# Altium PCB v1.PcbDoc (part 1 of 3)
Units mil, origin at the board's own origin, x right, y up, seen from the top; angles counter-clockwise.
Board outline 2610 x 5109 mil, 2 copper layers (Top Layer, Bottom Layer), stack 62 mil thick; 307 components, 181 nets, 763 pads, 1057 vias.
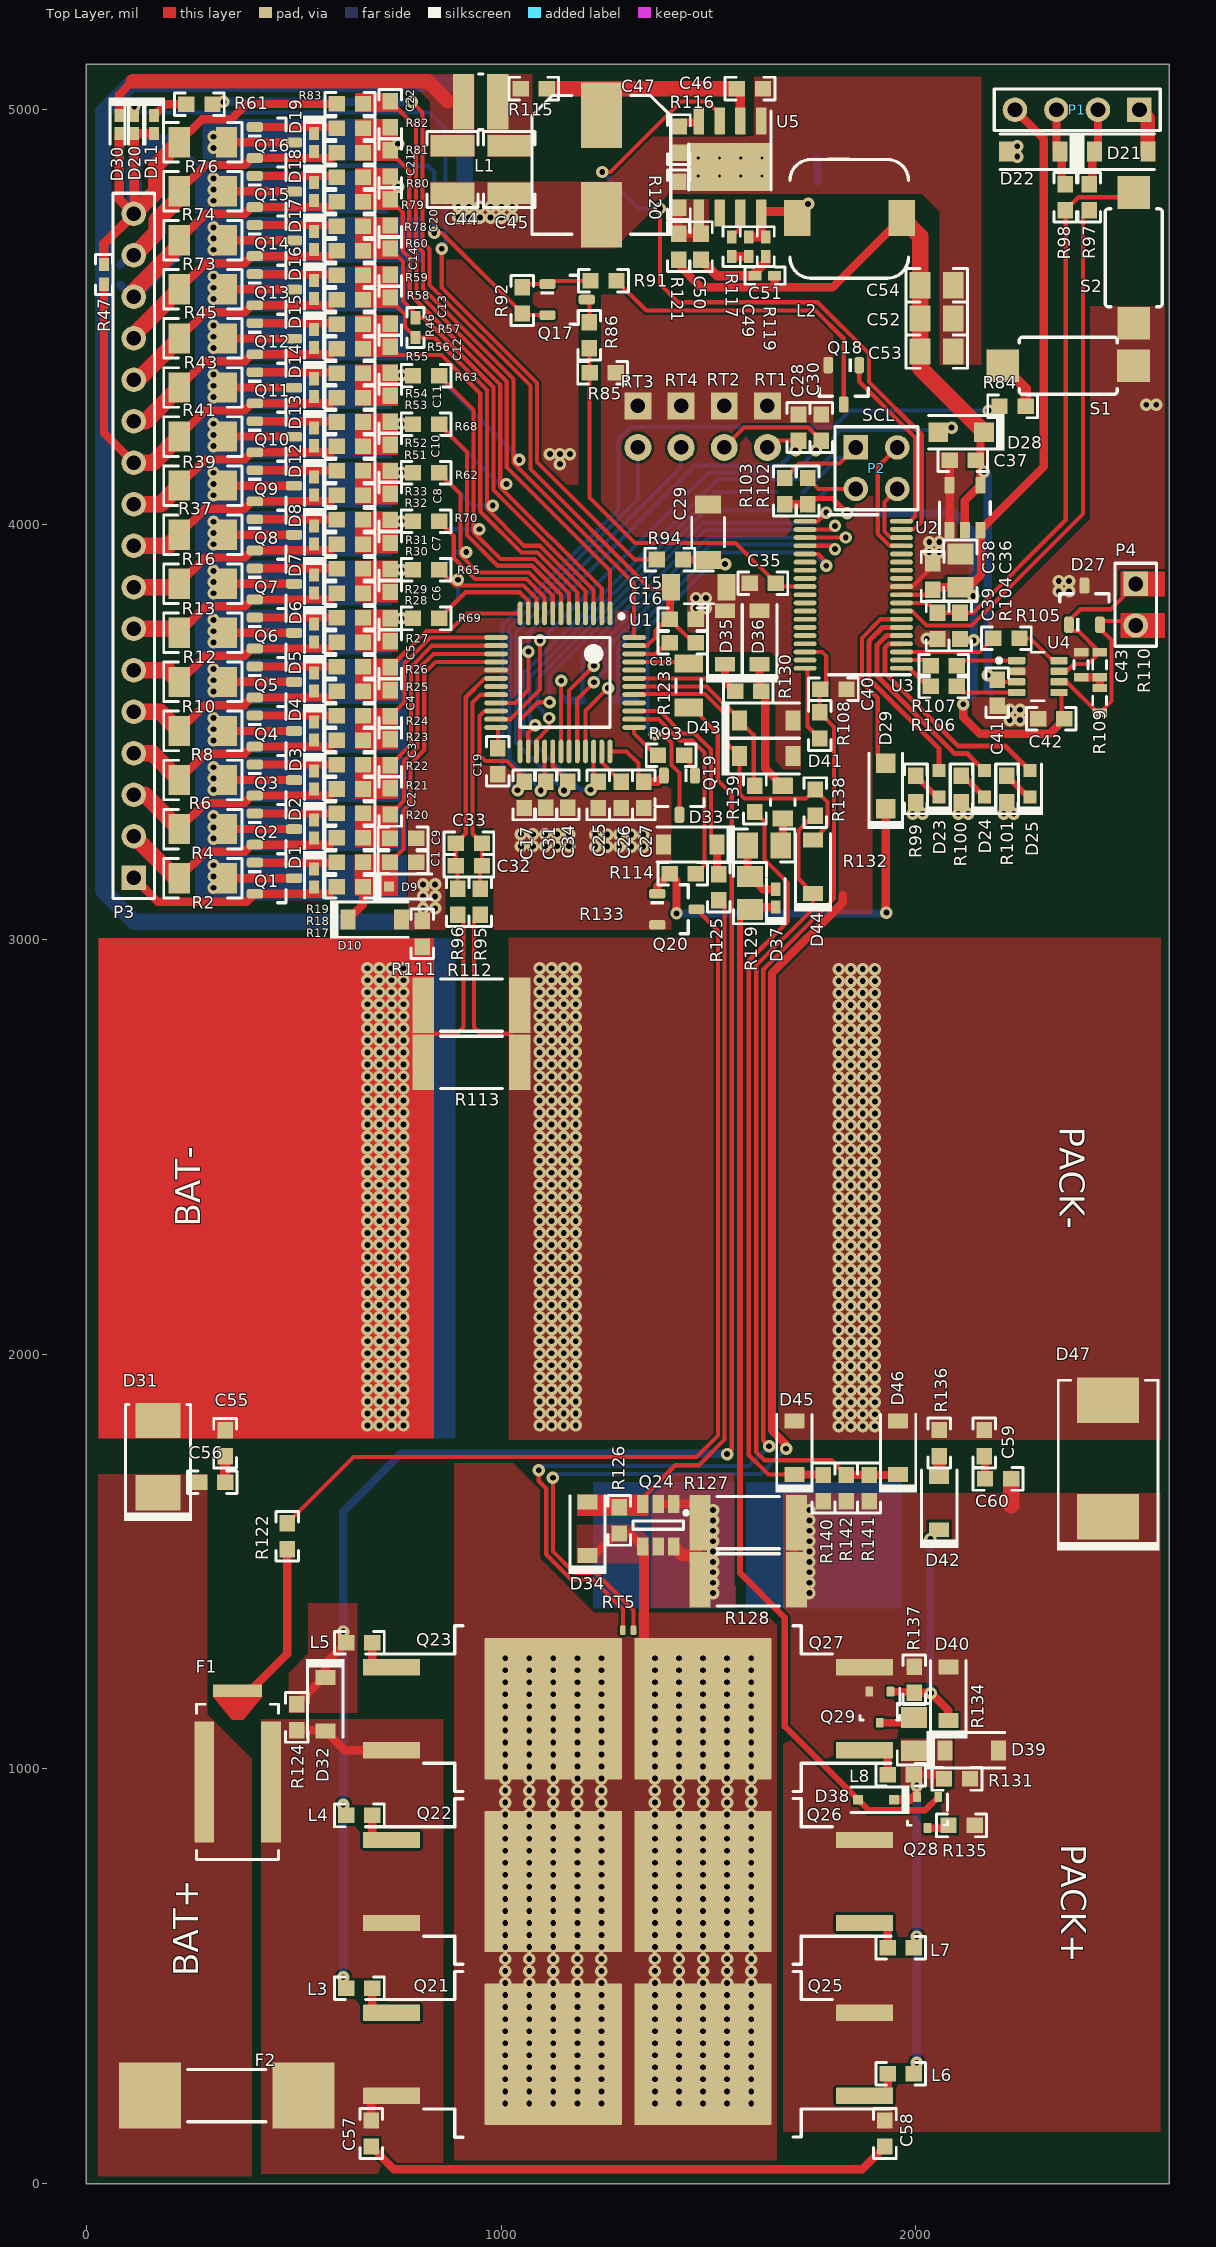
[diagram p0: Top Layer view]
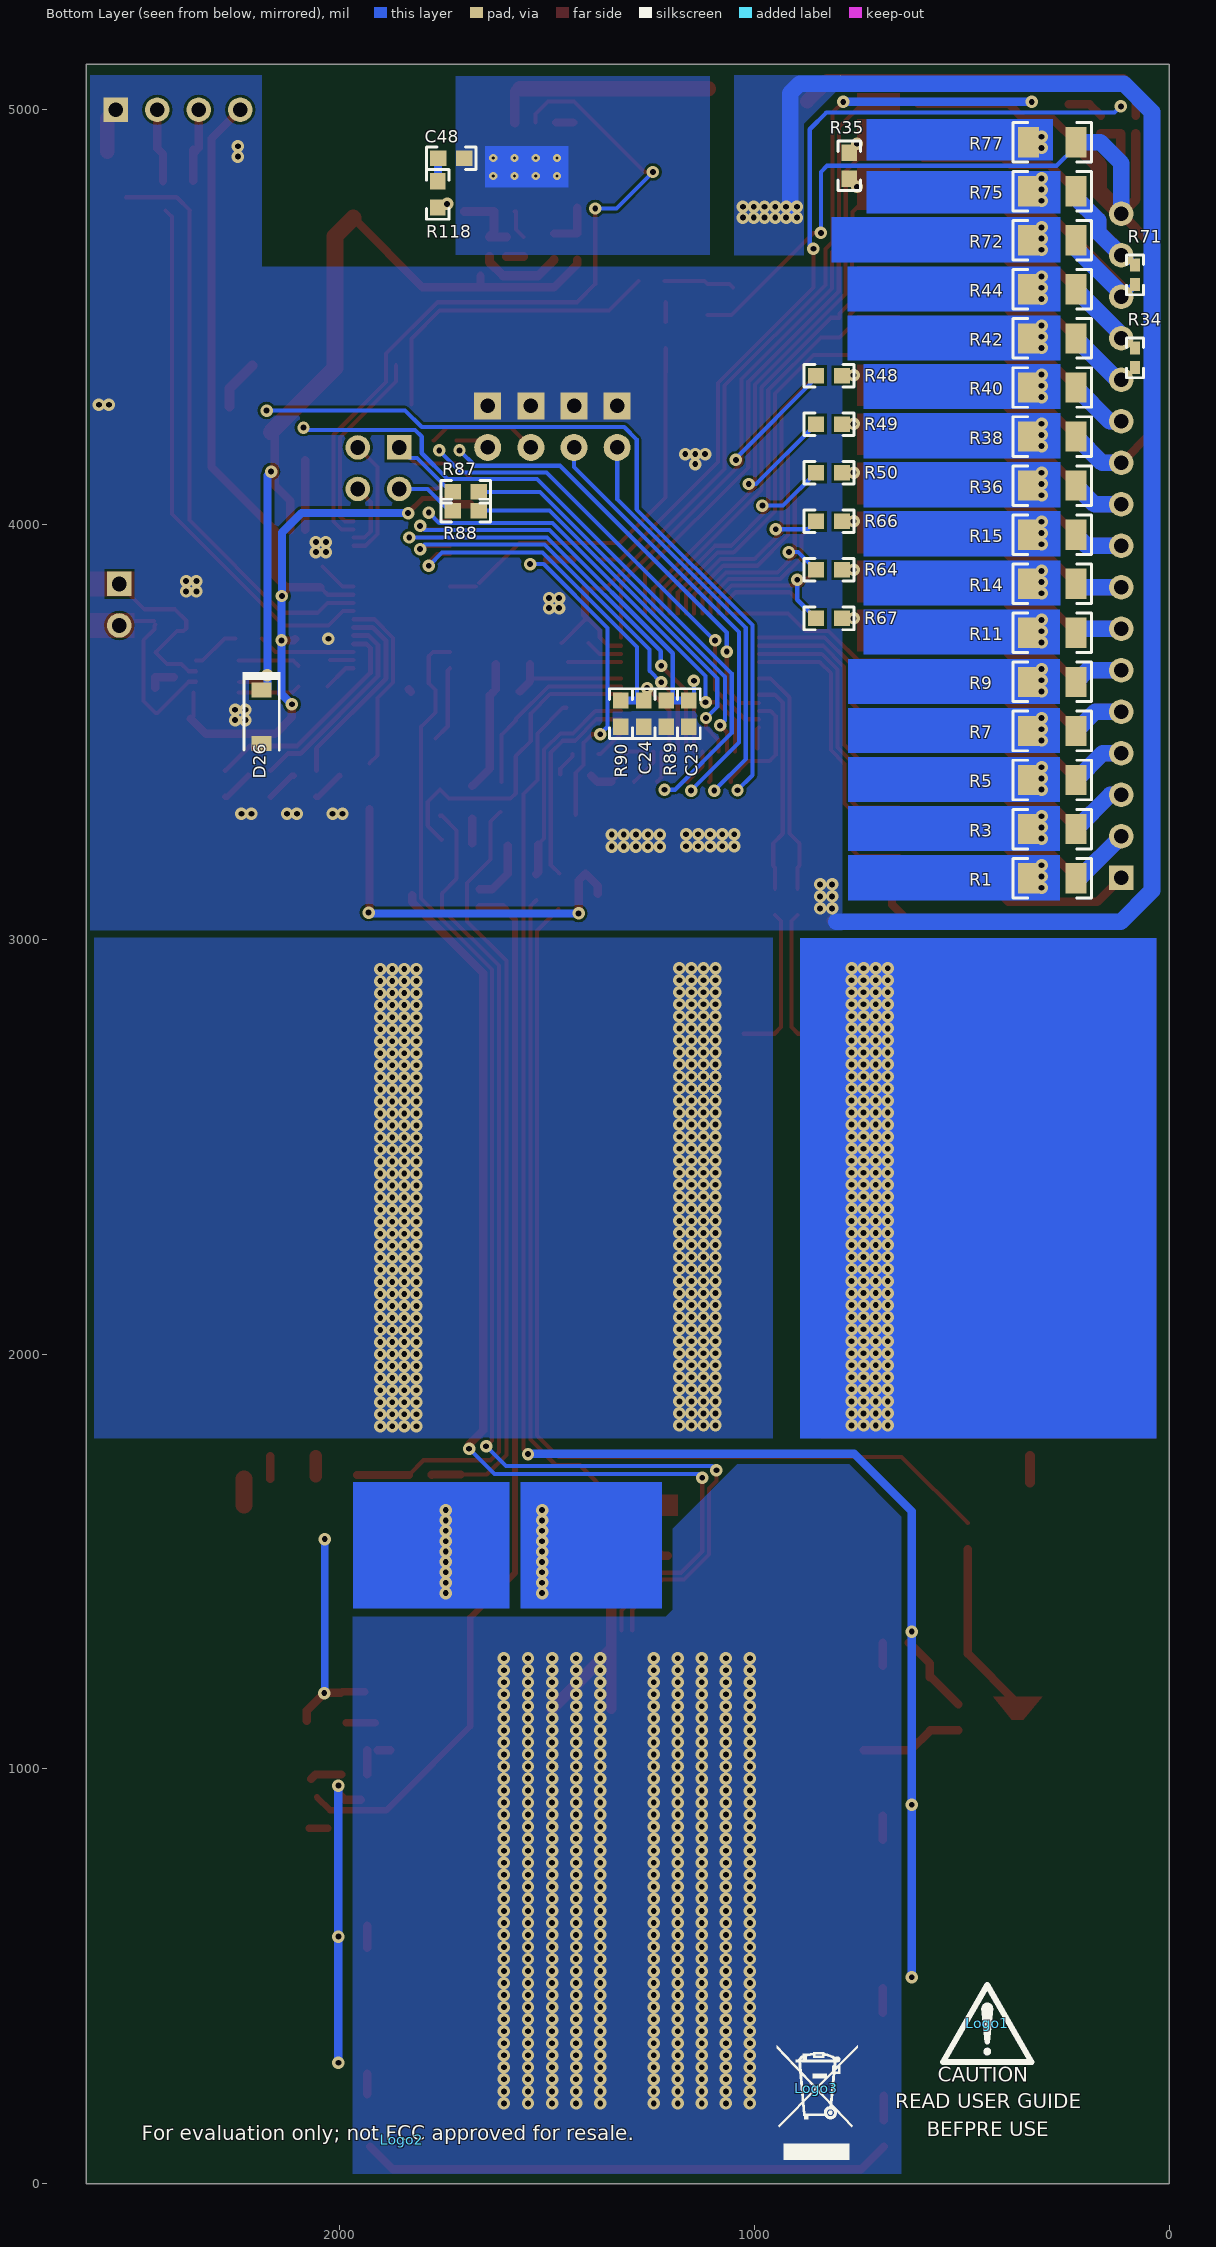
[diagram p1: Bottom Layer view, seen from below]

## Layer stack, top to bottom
Top Solder: solder mask 0.4, Solder Resist, Dk 3.5
Top Layer: signal copper 1.4
Dielectric1: core 59.2, FR-4, Dk 4.8
Bottom Layer: signal copper 1.4
Bottom Solder: solder mask 0.4, Solder Resist, Dk 3.5

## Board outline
0,0 0,5109 2610,5109 2610,0

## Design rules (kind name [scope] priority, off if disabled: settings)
AcuteAngle [All] p1: minimum=4.50000000000000E+0001 checktracksonly=FALSE
AssemblyTestPointUsage [All] p1: valid=2
BoardOutlineClearance BoardOutlineClearance_MountingHoles [OnCopper and InComponentClass('Mounting Holes')] p1 off: gap=40 ignorepadtopadclearanceinfootprint=FALSE
BoardOutlineClearance BoardOutlineClearance_Poly [OnCopper and IsPoly] p2 off: gap=25 ignorepadtopadclearanceinfootprint=FALSE
BoardOutlineClearance [OnCopper and Not InComponentClass('Logo') and not InComponentClass('FiducialMark') and not InRegion(1000,500,4000,800) and not InPoly] p3 off: gap=75 ignorepadtopadclearanceinfootprint=FALSE
Clearance Clearance_Keepouts [((IsTrack Or IsArc) And Not InPoly) And IsFree and IsKeepOut vs ((IsTrack Or IsArc) And Not InPoly) And IsFree and IsKeepOut] p1: gap=0 ignorepadtopadclearanceinfootprint=FALSE
Clearance Clearance_Poly [InPolygon] p2: gap=6 ignorepadtopadclearanceinfootprint=FALSE
Clearance Clearance_FiducialMark [IsKeepOut and InComponentClass('FiducialMark') vs IsPad and InComponentClass('FiducialMark')] p3: gap=0 ignorepadtopadclearanceinfootprint=FALSE
Clearance [All] p4: gap=6 ignorepadtopadclearanceinfootprint=FALSE
ComponentClearance ComponentClearance_MountingHoles_FiducialMarks [InComponentClass('Mounting Holes') vs InComponentClass('FiducialMark')] p1: gap=0 collisioncheckmode=3 verticalgap=10 showdistances=FALSE
ComponentClearance ComponentClearance_Shunt [InComponentClass('Header') vs InComponentClass('Shunt')] p2: gap=0 collisioncheckmode=3 verticalgap=0 showdistances=FALSE
ComponentClearance ComponentClearance_Logo [InComponentClass('Logo')] p3: gap=50 collisioncheckmode=3 verticalgap=10 showdistances=FALSE
ComponentClearance ComponentClearance_ScrewToNut [(HasFootprint('NY PMS 440 0025 PH')) vs (HasFootprint('Keystone_1902C'))] p4: gap=5 collisioncheckmode=3 verticalgap=10 showdistances=FALSE
ComponentClearance ComponentClearance_MountingHoles [InComponentClass('Mounting Holes')] p5: gap=6 collisioncheckmode=3 verticalgap=100000 showdistances=FALSE
ComponentClearance ComponentClearance_SmallPassives [HasFootprint('0201*') or HasFootprint('0402*') or HasFootprint('0508') or HasFootprint('0603*') or HasFootprint('0612') or HasFootprint('0805*') or HasFootprint('0815*') or HasFootprint('0830*') or HasFootprint('1206*') or HasFootprint('1210*') or HasFootprint('1808*') or HasFootprint('1812*') or HasFootprint('1825*') or HasFootprint('2010*') or HasFootprint('2220*') or HasFootprint('2225*') or HasFootprint('2512*') or HasFootprint('2728*') or HasFootprint('3518*') vs HasFootprint('0201*') or HasFootprint('0402*') or HasFootprint('0508') or HasFootprint('0603*') or HasFootprint('0612') or HasFootprint('0805*') or HasFootprint('0815*') or HasFootprint('0830*') or HasFootprint('1206*') or HasFootprint('1210*') or HasFootprint('1808*') or HasFootprint('1812*') or HasFootprint('1825*') or HasFootprint('2010*') or HasFootprint('2220*') or HasFootprint('2225*') or HasFootprint('2512*') or HasFootprint('2728*') or HasFootprint('3518*')] p6: gap=6 collisioncheckmode=3 verticalgap=10 showdistances=FALSE
ComponentClearance ComponentClearance_THtoSMT [IsThruComponent vs IsSMTComponent] p7: gap=6 collisioncheckmode=3 verticalgap=30 showdistances=FALSE
ComponentClearance ComponentClearance_THtoTH [IsThruComponent vs IsThruComponent] p8: gap=0 collisioncheckmode=3 verticalgap=30 showdistances=FALSE
ComponentClearance [All] p9: gap=0 collisioncheckmode=3 verticalgap=100000 showdistances=FALSE
DiffPairsRouting [All] p1: maxlimit=100 minlimit=10 mostfreqgap=10 toplayer_minwidth=15 toplayer_maxwidth=15 toplayer_prefwidth=15 bottomlayer_minwidth=15 bottomlayer_maxwidth=15 bottomlayer_prefwidth=15 maxuncoupledlength=1000
FabricationTestPointUsage TestPointUsage [All] p1: valid=2 allowmultiple=FALSE
FabricationTestpoint Testpoint [All] p1: side=3 testpointundercomponent=TRUE minsize=40 maxsize=100 preferedsize=60 minholesize=0 maxholesize=40 preferedholesize=32 testpointgrid=1 allowsidetop=TRUE allowsidebottom=TRUE usegrid=TRUE gridtolerance=0.01
FanoutControl Fanout_LCC [IsLCC] p1: bgadir=Out bgaviamode=Centered fanoutstyle=Auto fanoutdirection=Alternating viagrid=1 // Fanout_LCC (Default Rule)
FanoutControl Fanout_BGA [IsBGA] p2: bgadir=Out bgaviamode=Centered fanoutstyle=Auto fanoutdirection=Alternating viagrid=1 // Fanout_BGA (Default Rule)
FanoutControl Fanout_Default [All] p4: bgadir=Out bgaviamode=Centered fanoutstyle=Auto fanoutdirection=Alternating viagrid=1 // Fanout_Default (Default Rule)
FanoutControl Fanout_Small [(CompPinCount < 5)] p5: bgadir=Out bgaviamode=Centered fanoutstyle=Auto fanoutdirection=OutThenIn viagrid=1 // Fanout_Small (Default Rule)
HoleSize [All] p1: absolutevalues=TRUE maxlimit=251 minlimit=7.87 maxpercent=80.000 minpercent=20.000
MinimumAnnularRing MinimumAnnularRing_ThermalPadVias [IsVia and InAnyComponent] p1: minimumring=5.91
MinimumAnnularRing [All] p2: minimumring=8
MinimumSolderMaskSliver MinimumSolderMaskSliver_Logo [InComponentClass('Logo') vs InComponentClass('Logo')] p1 off: minsoldermaskwidth=0.7
MinimumSolderMaskSliver [All] p2 off: minsoldermaskwidth=3.94
PlaneConnect [All] p1: planeconnectstyle=Relief reliefexpansion=10 reliefentries=4 reliefconductorwidth=10 reliefairgap=10
PolygonConnect [All] p1: connectstyle=Direct reliefconductorwidth=10 reliefentries=4 polygonreliefangle="90 Angle" airgapwidth=10
RoutingVias ThermalPadVias [IsVia and InAnyComponent] p1: holewidth=7.87 width=19.68 viastyle="Through Hole" minholewidth=7.87 minwidth=19.68 maxholewidth=12.99 maxwidth=23.62
RoutingVias [All] p2: holewidth=16 width=34 viastyle="Through Hole" minholewidth=7.87 minwidth=26 maxholewidth=40 maxwidth=65
SilkToBoardRegionClearance [Not ((IsComment or IsDesignator) And (Hide <> 'False')) and not InRegion(1000,500,4000,800)] p1:
SilkToSilkClearance SilkToSilkClearance_Pb-FreeLogo [(HasFootprint('Pb-Free_Overlay_Medium') OR HasFootprint('Pb-Free_Overlay_Small')) vs (HasFootprint('Pb-Free_Overlay_Medium') OR HasFootprint('Pb-Free_Overlay_Small'))] p1 off: silktosilkclearance=0
SilkToSilkClearance [All] p2 off: silktosilkclearance=4
SilkToSolderMaskClearance SilkToComponentPadClearance [(IsPad or IsFill or IsRegion) and InAnycomponent] p1 off: minsilkscreentomaskgap=5 clearancetoexposedcopper=TRUE
SilkToSolderMaskClearance "Silk to Solder Mask Opening" [All] p2 off: minsilkscreentomaskgap=4 clearancetoexposedcopper=FALSE
SolderMaskExpansion [All] p1: expansion=1.97
Width [All] p1: maxlimit=100 minlimit=6 preferedwidth=10 checkconnectedcopper=TRUE
15 further rules are at their usual default settings.

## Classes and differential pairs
component class "High level sch": D28 D29 P3 P4 R111 R112 R113 R114
component class Designator: C1 C2 C3 C4 C5 C6 C7 C8 C9 C10 C11 C12 C13 C14 C15 C16 C17 C18 C19 C20 C21 C22 C23 C24 C25 C26 C27 C28 C29 C30 C31 C32 C33 C34 D1 D2 D3 D4 D5 D6 D7 D8 D9 D10 D11 D12 D13 D14 D15 D16 D17 D18 D19 D20 Q1 Q2 Q3 Q4 Q5 Q6 Q7 Q8 Q9 Q10 Q11 Q12 Q13 Q14 Q15 Q16 Q17 Q18 Q19 R1 R2 R3 R4 R5 R6 R7 R8 R9 R10 R11 R12 R13 R14 R15 R16 R17 R18 R19 R20 R21 R22 R23 R24 R25 R26 R27 R28 R29 R30 R31 R32 R33 R34 R35 R36 R37 R38 R39 R40 R41 R42 R43 R44 R45 R46 R47 R48 R49 R50 R51 R52 R53 R54 R55 R56 R57 R58 R59 R60 R61 R62 R63 R64 R65 R66 R67 R68 R69 R70 R71 R72 R73 R74 R75 R76 R77 R78 R79 R80 R81 R82 R83 R84 R85 R86 R87 R88 R89 R90 R91 R92 R93 R94 R95 R96 RT1 RT2 RT3 RT4 S1 U1

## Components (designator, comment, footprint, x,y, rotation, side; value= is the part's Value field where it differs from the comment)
C1 "GCM188R71H224KA64D" 0603 764,3185 r0 top value=0.22uF
C2 "GCM188R71H224KA64D" 0603 733,3332 r270 top value=0.22uF
C3 "GCM188R71H224KA64D" 0603 733,3450.29 r270 top value=0.22uF
C4 "GCM188R71H224KA64D" 0603 733,3568.57 r270 top value=0.22uF
C5 "GCM188R71H224KA64D" 0603 733,3686.86 r270 top value=0.22uF
C6 "GCM188R71H224KA64D" 0603 733,3805.14 r270 top value=0.22uF
C7 "GCM188R71H224KA64D" 0603 733,3923.43 r270 top value=0.22uF
C8 "GCM188R71H224KA64D" 0603 733,4041.71 r270 top value=0.22uF
C9 "GCM188R71H224KA64D" 0603 764,3243 r0 top value=0.22uF
C10 "GCM188R71H224KA64D" 0603 733,4160 r270 top value=0.22uF
C11 "GCM188R71H224KA64D" 0603 733,4278.29 r270 top value=0.22uF
C12 "GCM188R71H224KA64D" 0603 733,4396.57 r270 top value=0.22uF
C13 "GCM188R71H224KA64D" 0603 733,4514.86 r270 top value=0.22uF
C14 "GCM188R71H224KA64D" 0603 733,4633.14 r270 top value=0.22uF
C15 "CL31B225KCHSNNE" 1206_190 1477,3848 r180 top value=2.2uF
C16 "GRM1885C2A101JA01D" 0603 1438,3771 r180 top value=100pF
C17 "GRM1885C2A101JA01D" 0603 1056.34,3347.73 r270 top value=100pF
C18 "C1608X7R1E105K080AB" 0603 1438,3714 r0 top value=1uF
C19 "EMK107BB7225MA-T" 0603 992.34,3428.73 r270 top value=2.2uF
C20 "GCM188R71H224KA64D" 0603 733,4751.43 r270 top value=0.22uF
C21 "GCM188R71H224KA64D" 0603 733,4869.71 r270 top value=0.22uF
C22 "GCM188R71H224KA64D" 0603 733,4988 r270 top value=0.22uF
C23 "GRM1885C2A101JA01D" 0603 1157,3543.5 r270 bottom value=100pF
C24 "GRM1885C2A101JA01D" 0603 1266.38,3543.5 r270 bottom value=100pF
C25 "GCM188R71C105KA64D" 0603 1234.34,3347.73 r270 top value=1uF
C26 "GCM188R71C105KA64D" 0603 1289.34,3347.73 r270 top value=1uF
C27 "GRM188R71H223KA01D" 0603 1344,3347.73 r270 top value=0.022uF
C28 "GRM188R71H471KA01D" 0603 1717,4233.01 r90 top value=470pF
C29 "C3216X7R2A105K160AA" 1206_180 1499,3981 r90 top value=1uF
C30 "GRM188R71H471KA01D" 0603 1772,4233.01 r90 top value=470pF
C31 "GRM188R71H471KA01D" 0603 1108,3348 r270 top value=470pF
C32 "GRM188R71H104KA93D" 0603 922.5,3177 r0 top value=0.1uF
C33 "GRM1885C2A101JA01D" 0603 922.5,3231 r0 top value=100pF
C34 "GRM188R71H471KA01D" 0603 1161,3348 r270 top value=470pF
C35 "GRM188R71H471KA01D" 0603 1631,3858 r0 top value=470pF
C36 "CL21B106KOQNNNE" 0805_HV 2107,3888 r270 top value=10uF
C37 "EMK107BB7225MA-T" 0603 2113,4154 r180 top value=2.2uF
C38 "GRM188R71H104KA93D" 0603 2040,3873.98 r270 top value=0.1uF
C39 "GRM1885C1H102JA01D" 0603 2052,3755 r270 top value=1000pF
C40 "GRM188R71H471KA01D" 0603 1801,3602 r0 top value=470pF
C41 "GRM188R71H104KA93D" 0603 2196,3594 r270 top value=0.1uF
C42 "GRM188R71H104KA93D" 0603 2326,3531 r180 top value=0.1uF
C43 "GRM188R71H104KA93D" 0603S 2398,3661.33 r270 top value=0.1uF
C44 "C3225X7S2A475K200AE" 1210 883,4855 r270 top value=4.7uF
C45 "C3225X7S2A475K200AE" 1210 1020,4855 r270 top value=4.7uF
C46 "GRM188R72A104KA35D" 0603 1600,5050 r0 top value=0.1uF
C47 "UUX2A100MNL1GS" UUX_800x620 1242,4866 r270 top value=10uF
C48 "NC" 0603 1730,4882 r180 bottom value=56pF
C49 "GRM155R71H222KA01D" 0402 1597,4669 r90 top value=2200pF
C50 "GRM1885C1H101JA01D" 0603 1482,4669 r90 top value=100pF
C51 "GRM155R71H152KA01D" 0402 1636,4599 r180 top value=1500pF
C52 "GRM21BR71C475KA73L" 0805_HV 2050,4496 r0 top value=4.7uF
C53 "GRM21BR71C475KA73L" 0805_HV 2050,4416 r0 top value=4.7uF
C54 "GRM21BR71C475KA73L" 0805_HV 2050,4576 r0 top value=4.7uF
C55 "GRM188R72A104KA35D" 0603 335,1785 r90 top value=0.1uF
C56 "GRM188R72A104KA35D" 0603 304,1691 r0 top value=0.1uF
C57 "GRM188R72A104KA35D" 0603 687.34,121.51 r90 top value=0.1uF
C58 "GRM188R72A104KA35D" 0603 1925.2,121.51 r270 top value=0.1uF
C59 "GRM188R72A104KA35D" 0603 2164.87,1785.52 r90 top value=0.1uF
C60 "GRM188R72A104KA35D" 0603 2198,1699 r180 top value=0.1uF
D1 "BZT52C5V6T-7" SOD-523 549,3147 r270 top value=5.6V
D2 "BZT52C5V6T-7" SOD-523 549,3265.2 r270 top value=5.6V
D3 "BZT52C5V6T-7" SOD-523 549,3383.4 r270 top value=5.6V
D4 "BZT52C5V6T-7" SOD-523 549,3501.6 r270 top value=5.6V
D5 "BZT52C5V6T-7" SOD-523 549,3619.8 r270 top value=5.6V
D6 "BZT52C5V6T-7" SOD-523 549,3738 r270 top value=5.6V
D7 "BZT52C5V6T-7" SOD-523 549,3856.2 r270 top value=5.6V
D8 "BZT52C5V6T-7" SOD-523 549,3974.4 r270 top value=5.6V
D9 "BAT42WS-7-F" SOD-323 773,3127 r0 top value=30V
D10 "MMSZ4685T1G" SOD-123 696,3047 r0 top value=3.6V
D11 "BAS516,115" SOD-523 164,4963 r270 top value=100V
D12 "BZT52C5V6T-7" SOD-523 549,4092.6 r270 top value=5.6V
D13 "BZT52C5V6T-7" SOD-523 549,4210.8 r270 top value=5.6V
D14 "BZT52C5V6T-7" SOD-523 549,4329 r270 top value=5.6V
D15 "BZT52C5V6T-7" SOD-523 549,4447.2 r270 top value=5.6V
D16 "BZT52C5V6T-7" SOD-523 549,4565.4 r270 top value=5.6V
D17 "BZT52C5V6T-7" SOD-523 549,4683.6 r270 top value=5.6V
D18 "BZT52C5V6T-7" SOD-523 549,4801.8 r270 top value=5.6V
D19 "BZT52C5V6T-7" SOD-523 549,4920 r270 top value=5.6V
D20 "BAS516,115" SOD-523 116,4963 r270 top value=100V
D21 "MMSZ4685T1G" SOD-123 2494.7,4897.95 r0 top value=3.6V
D22 "MMSZ4685T1G" SOD-123 2282.7,4897.95 r180 top value=3.6V
D23 "150060RS75000" WL-SMCW_RED 2055.18,3374.5 r90 top value=Red
D24 "150060RS75000" WL-SMCW_RED 2165,3374.5 r90 top value=Red
D25 "150060RS75000" WL-SMCW_RED 2274.82,3374.5 r90 top
D26 "MMSZ4690T1G" SOD-123 2187,3536 r270 bottom value=5.6V
D27 "NUP3105LT1G" SOT-23 2406,3805 r90 top value=24V
D28 "PMEG2010AEH,115" SOD-123F 2109,4222 r180 top value=20V
D29 "PMEG2010AEH,115" SOD-123F 1927,3369 r90 top value=20V
D30 "BAS516,115" SOD-523 80,4963 r270 top value=100V
D31 "SMBJ60A-13-F" SMB 173,1753 r90 top value=60V
D32 "MMSZ5246B-7-F" SOD-123 576.52,1156.51 r270 top value=16V
D33 "MMSZ5267BT1G" SOD-123 1456,3228 r180 top value=75V
D34 "MMSZ5246B-7-F" SOD-123 1208.48,1578.47 r90 top value=16V
D35 "NC" SOD-123 1540,3727 r90 top value=75V
D36 "BAT46W-7-F" SOD-123 1623,3727 r90 top value=100V
D37 "BAS516,115" SOD-523 1662,3098.7 r90 top value=100V
D38 "BZT52C5V1S-7-F" SOD-323 1904,926 r180 top value=5.1V
D39 "MMSZ5246B-7-F" SOD-123 2134,1045 r0 top value=16V
D40 "MMSZ5246B-7-F" SOD-123 2078,1181 r90 top value=16V
D41 "MMSZ5267BT1G" SOD-123 1639,3441 r0 top value=75V
D42 "BAT46W-7-F" SOD-123 2056,1641 r90 top value=100V
D43 "MMSZ5267BT1G" SOD-123 1639,3527 r0 top value=75V
D44 "BAT46W-7-F" SOD-123 1752,3175 r90 top value=100V
D45 "BAT46W-7-F" SOD-123 1707,1774 r90 top value=100V
D46 "BAT46W-7-F" SOD-123 1957,1774 r90 top value=100V
D47 "ES3D-E3/57T" SMC 2463,1748 r90 top value=200V
F1 "NC" FUSE_SFK-xx30x 365,969 r270 top
F2 "0678L9300-02" Fuse_0678L 339,213 r180 top
L1 "74438335010" WE-MAPI_3015 951,5018 r0 top value=1uH
L2 "744777168" WE-PD_7345 1840,4738 r0 top value=68uH
L3 "74279265" 0603 658.52,471.51 r0 top value="600 ohm"
L4 "74279265" 0603 658.52,888.01 r0 top value="600 ohm"
L5 "74279265" 0603 658.52,1304.51 r0 top value="600 ohm"
L6 "74279265" 0603 1963.52,265.51 r180 top value="600 ohm"
L7 "74279265" 0603 1963.52,569.51 r180 top value="600 ohm"
L8 "74279265" 0603 1963.52,986.51 r180 top value="600 ohm"
Logo1 "CAUTION.  READ USER GUIDE BEFORE USE" IEC_Caution_Small 438,387 r180 bottom
Logo2 "FCC disclaimer" FCC_disclaimer 1849,107 r180 bottom
Logo3 "WEEE logo" WEEE_Minimum 850,230 r180 bottom
P1 "Header 4" HDR1X4 2538.7,4998.95 r180 top
P2 "Header 2X2" HDR2X2 1855,4185 r270 top
P3 "Header 17" HDR1X17 115,3148 r90 top
P4 "Header 2" HDR1X2 2530,3856 r270 top
Q1 "DMG2302UK-7" SOT-23 454,3147 r0 top value=20V
Q2 "DMG2302UK-7" SOT-23 454,3265.2 r0 top value=20V
Q3 "DMG2302UK-7" SOT-23 454,3383.4 r0 top value=20V
Q4 "DMG2302UK-7" SOT-23 454,3501.6 r0 top value=20V
Q5 "DMG2302UK-7" SOT-23 454,3619.8 r0 top value=20V
Q6 "DMG2302UK-7" SOT-23 454,3738 r0 top value=20V
Q7 "DMG2302UK-7" SOT-23 454,3856.2 r0 top value=20V
Q8 "DMG2302UK-7" SOT-23 454,3974.4 r0 top value=20V
Q9 "DMG2302UK-7" SOT-23 454,4092.6 r0 top value=20V
Q10 "DMG2302UK-7" SOT-23 454,4210.8 r0 top value=20V
Q11 "DMG2302UK-7" SOT-23 454,4329 r0 top value=20V
Q12 "DMG2302UK-7" SOT-23 454,4447.2 r0 top value=20V
Q13 "DMG2302UK-7" SOT-23 454,4565.4 r0 top value=20V
Q14 "DMG2302UK-7" SOT-23 454,4683.6 r0 top value=20V
Q15 "DMG2302UK-7" SOT-23 454,4801.8 r0 top value=20V
Q16 "DMG2302UK-7" SOT-23 454,4920 r0 top value=20V
Q17 "ZXMP10A13FTA" SOT-23 1159.3,4541.32 r0 top value=-100V
Q18 "BSS123" SOT-23 1826,4336 r270 top value=100V
Q19 "ZXTN25100BFHTA" SOT-23 1430,3347 r270 top value="100 V"
Q20 "DMN10H220L-7" SOT-23 1424,3072 r0 top value=100V
Q21 "CSD19536KTT" KTT0002A_N 978.43,312.4 r0 top value=100V
Q22 "CSD19536KTT" KTT0002A_N 978.43,728.9 r0 top value=100V
Q23 "CSD19536KTT" KTT0002A_N 978.43,1145.4 r0 top value=100V
Q24 "FDC3535" SSOT-6 1379,1587.82 r270 top value=-80V
Q25 "CSD19536KTT" KTT0002A_N 1634.12,312.5 r180 top value=100V
Q26 "CSD19536KTT" KTT0002A_N 1634.12,729 r180 top value=100V
Q27 "CSD19536KTT" KTT0002A_N 1634.12,1145.5 r180 top value=100V
Q28 "DMG1013UW-7" SOT-323 2028,895 r270 top value=-20V
Q29 "2N7002W-7-F" SOT-323 1913,1149 r270 top value=60V
R1 "CRCW120680R6FKEA" 1206 281.53,3147 r0 bottom value=80.6
R2 "CRCW120680R6FKEA" 1206 281.53,3147 r0 top value=80.6
R3 "CRCW120680R6FKEA" 1206 281.53,3265.26 r0 bottom value=80.6
R4 "CRCW120680R6FKEA" 1206 281.53,3265.26 r0 top value=80.6
R5 "CRCW120680R6FKEA" 1206 281.53,3383.51 r0 bottom value=80.6
R6 "CRCW120680R6FKEA" 1206 281.53,3383.51 r0 top value=80.6
R7 "CRCW120680R6FKEA" 1206 281.53,3501.77 r0 bottom value=80.6
R8 "CRCW120680R6FKEA" 1206 281.53,3501.77 r0 top value=80.6
R9 "CRCW120680R6FKEA" 1206 281.53,3620.03 r0 bottom value=80.6
R10 "CRCW120680R6FKEA" 1206 281.53,3620.03 r0 top value=80.6
R11 "CRCW120680R6FKEA" 1206 281.53,3738.29 r0 bottom value=80.6
R12 "CRCW120680R6FKEA" 1206 281.53,3738.29 r0 top value=80.6
R13 "CRCW120680R6FKEA" 1206 281.53,3856.54 r0 top value=80.6
R14 "CRCW120680R6FKEA" 1206 281.53,3856.54 r0 bottom value=80.6
R15 "CRCW120680R6FKEA" 1206 281.53,3974.8 r0 bottom value=80.6
R16 "CRCW120680R6FKEA" 1206 281.53,3974.8 r0 top value=80.6
R17 "CRCW0603100RFKEA" 0603 636,3126 r0 top value=100
R18 "CRCW060310K0JNEA" 0603 636,3184.97 r0 top value=10k
R19 "CRCW0603100RFKEA" 0603 636,3243.94 r0 top value=100
R20 "CRCW060310K0JNEA" 0603 636,3302.9 r0 top value=10k
R21 "CRCW0603100RFKEA" 0603 636,3361.87 r0 top value=100
R22 "CRCW060310K0JNEA" 0603 636,3420.84 r0 top value=10k
R23 "CRCW0603100RFKEA" 0603 636,3479.81 r0 top value=100
R24 "CRCW060310K0JNEA" 0603 636,3538.77 r0 top value=10k
R25 "CRCW0603100RFKEA" 0603 636,3597.74 r0 top value=100
R26 "CRCW060310K0JNEA" 0603 636,3656.71 r0 top value=10k
R27 "CRCW0603100RFKEA" 0603 636,3715.68 r0 top value=100
R28 "CRCW060310K0JNEA" 0603 636,3774.64 r0 top value=10k
R29 "CRCW0603100RFKEA" 0603 636,3833.61 r0 top value=100
R30 "CRCW060310K0JNEA" 0603 636,3892.58 r0 top value=10k
R31 "CRCW0603100RFKEA" 0603 636,3951.55 r0 top value=100
R32 "CRCW060310K0JNEA" 0603 636,4010.52 r0 top value=10k
R33 "CRCW0603100RFKEA" 0603 636,4069.48 r0 top value=100
R34 "CRCW04020000Z0ED" 0402 82,4401 r90 bottom value=0
R35 "CRCW06030000Z0EA" 0603 771,4864 r270 bottom value=0
R36 "CRCW120680R6FKEA" 1206 281.53,4093.06 r0 bottom value=80.6
R37 "CRCW120680R6FKEA" 1206 281.53,4093.06 r0 top value=80.6
R38 "CRCW120680R6FKEA" 1206 281.53,4211.32 r0 bottom value=80.6
R39 "CRCW120680R6FKEA" 1206 281.53,4211.32 r0 top value=80.6
R40 "CRCW120680R6FKEA" 1206 281.53,4329.57 r0 bottom value=80.6
R41 "CRCW120680R6FKEA" 1206 281.53,4329.57 r0 top value=80.6
R42 "CRCW120680R6FKEA" 1206 281.53,4447.83 r0 bottom value=80.6
R43 "CRCW120680R6FKEA" 1206 281.53,4447.83 r0 top value=80.6
R44 "CRCW120680R6FKEA" 1206 281.53,4566.09 r0 bottom value=80.6
R45 "CRCW120680R6FKEA" 1206 281.53,4566.09 r0 top value=80.6
R46 "CRCW04020000Z0ED" 0402 794,4474 r90 top value=0
R47 "CRCW04020000Z0ED" 0402 43,4602 r270 top value=0
R48 "CRCW06030000Z0EA" 0603 819.5,4358 r0 bottom value=0
R49 "CRCW06030000Z0EA" 0603 819.5,4241 r0 bottom value=0
R50 "CRCW06030000Z0EA" 0603 819.5,4124 r0 bottom value=0
R51 "CRCW060310K0JNEA" 0603 636,4128.45 r0 top value=10k
R52 "CRCW0603100RFKEA" 0603 636,4187.42 r0 top value=100
R53 "CRCW060310K0JNEA" 0603 636,4246.39 r0 top value=10k
R54 "CRCW0603100RFKEA" 0603 636,4305.35 r0 top value=100
R55 "CRCW060310K0JNEA" 0603 636,4364.32 r0 top value=10k
R56 "CRCW0603100RFKEA" 0603 636,4423.29 r0 top value=100
R57 "CRCW060310K0JNEA" 0603 636,4482.26 r0 top value=10k
R58 "CRCW0603100RFKEA" 0603 636,4541.22 r0 top value=100
R59 "CRCW060310K0JNEA" 0603 636,4600.19 r0 top value=10k
R60 "CRCW0603100RFKEA" 0603 636,4659.16 r0 top value=100
R61 "CRCW0603100RFKEA" 0603 273,5012 r0 top value=100
R62 "CRCW06030000Z0EA" 0603 819.5,4123.97 r0 top value=0
R63 "CRCW06030000Z0EA" 0603 819.5,4358 r0 top value=0
R64 "CRCW06030000Z0EA" 0603 819.5,3890 r0 bottom value=0
R65 "CRCW06030000Z0EA" 0603 819.5,3890.01 r180 top value=0
R66 "CRCW06030000Z0EA" 0603 819.5,4007 r0 bottom value=0
R67 "CRCW06030000Z0EA" 0603 819.5,3773 r0 bottom value=0
R68 "CRCW06030000Z0EA" 0603 819.5,4241.05 r180 top value=0
R69 "CRCW06030000Z0EA" 0603 819.5,3773 r180 top value=0
R70 "CRCW06030000Z0EA" 0603 819.5,4007.03 r180 top value=0
R71 "CRCW04020000Z0ED" 0402 82,4601 r90 bottom value=0
R72 "CRCW120680R6FKEA" 1206 281.53,4684.34 r0 bottom value=80.6
R73 "CRCW120680R6FKEA" 1206 281.53,4684.34 r0 top value=80.6
R74 "CRCW120680R6FKEA" 1206 281.53,4802.6 r0 top value=80.6
R75 "CRCW120680R6FKEA" 1206 281.53,4802.6 r0 bottom value=80.6
R76 "CRCW120680R6FKEA" 1206 281.53,4920.86 r0 top value=80.6
R77 "CRCW120680R6FKEA" 1206 281.53,4920.86 r0 bottom value=80.6
R78 "CRCW060310K0JNEA" 0603 636,4718.13 r0 top value=10k
R79 "CRCW0603100RFKEA" 0603 636,4777.1 r0 top value=100
R80 "CRCW060310K0JNEA" 0603 636,4836.06 r0 top value=10k
R81 "CRCW0603100RFKEA" 0603 636,4895.03 r0 top value=100
R82 "CRCW060310K0JNEA" 0603 636,4954 r0 top value=10k
R83 "CRCW0603100RFKEA" 0603 636,5013 r0 top value=100
R84 "CRCW060310K0JNEA" 0603 2233,4284 r180 top value=10k
R85 "RT0603DRE0713K3L" 0603 1245,4365.5 r180 top value=13.3k
R86 "RT0603DRE07665KL" 0603 1213,4455.5 r90 top value=665k
R87 "CRCW0603100RFKEA" 0603 1695,4078 r180 bottom value=100
R88 "CRCW0603100RFKEA" 0603 1695,4033 r180 bottom value=100
R89 "CRCW060310K0JNEA" 0603 1211.62,3543.5 r90 bottom value=10k
R90 "CRCW060310K0JNEA" 0603 1321,3543.5 r90 bottom value=10k
R91 "CRCW06033M30JNEA" 0603 1247,4586.5 r180 top value=3.3Meg
R92 "CRCW06031M00JNEA" 0603 1051.3,4539.32 r270 top value=1.0Meg
R93 "CRCW0603100RFKEA" 0603 1410,3443 r0 top value=100
R94 "RC0603FR-07249RL" 0603 1407,3915 r180 top value=249
R95 "CRCW0603100RFKEA" 0603 949.5,3090 r90 top value=100
R96 "CRCW0603100RFKEA" 0603 895.5,3090 r90 top value=100
R97 "CRCW0603100RFKEA" 0603 2417.47,4787.95 r90 top value=100
R98 "CRCW0603100RFKEA" 0603 2360,4787.95 r90 top value=100
R99 "RC0603FR-07470RL" 0603 1999.54,3362.19 r90 top value=470
R100 "RC0603FR-07470RL" 0603 2109.36,3362.19 r90 top value=470
R101 "RC0603FR-07470RL" 0603 2219.18,3362.19 r90 top value=470
R102 "CRCW060310K0JNEA" 0603 1739,4080 r90 top value=10k
R103 "CRCW060310K0JNEA" 0603 1684,4080 r90 top value=10k
R104 "RC0603FR-0747KL" 0603 2106.2,3755 r270 top value=47.0k
R105 "CRCW0603100RFKEA" 0603 2218,3725 r180 top value=100
R106 "CRCW0603100RFKEA" 0603 2067,3609 r180 top value=100
R107 "CRCW0603100RFKEA" 0603 2067,3659 r180 top value=100
R108 "CRCW060310K0FKEA" 0603 1768,3515 r270 top value=10.0k
R109 "RC0603FR-0760R4L" 0603S 2443,3575.33 r270 top value=60.4
R110 "RC0603FR-0760R4L" 0603S 2443,3661.33 r270 top value=60.4
R111 "CRCW06030000Z0EA" 0603 810,3013 r270 top value=0
R112 "CSNL2512FT2L00" 2512 929,2841 r0 top value=0.002
R113 "CSNL2512FT2L00" 2512 929,2703 r0 top value=0.002
R114 "CRCW06035K10JNEA" 0603 1438,3158 r180 top value=5.1k
R115 "CRCW06030000Z0EA" 0603 1079,5050 r0 top value=0
R116 "CRCW060382K5FKEA" 0603 1429,4927 r90 top value=82.5k
R117 "CRCW04020000Z0ED" 0402 1556,4669 r270 top value=0
R118 "NC" 0603 1762.78,4795 r270 bottom value=499k
R119 "RC0402FR-07523KL" 0402 1638,4669 r270 top value=523k
R120 "CRCW060363K4FKEA" 0603 1428.93,4794 r270 top value=63.4k
R121 "CRCW0603200KFKEA" 0603 1428.93,4669 r270 top value=200k
R122 "CRCW0603200RFKEA" 0603 485,1561 r90 top value=200
R123 "ERJ-8ENF4990V" 1206L 1452,3611 r270 top value=499
R124 "CRCW060310M0JNEA" 0603 507.52,1124.51 r270 top value=10Meg
R125 "RT0603BRD0749K9L" 0603 1525,3125.22 r270 top value=49.9k
R126 "CRCW06031M00JNEA" 0603 1285.11,1599.14 r270 top value=1.0Meg
R127 "RC2512JK-07510RL" 2512 1596,1594 r180 top value=510
R128 "RC2512JK-07510RL" 2512 1596,1456 r180 top value=510
R129 "RC0805JR-0756KL" 0805_HV 1600,3111.2 r270 top value=56k
R130 "CRCW0603100RFKEA" 0603 1596,3597 r0 top value=100
R131 "CRCW060310M0JNEA" 0603 2099,976 r0 top value=10Meg
R132 "CRCW0805511RFKEA" 0805_HV1 1679,3330 r270 top value=511
R133 "CRCW0805511RFKEA" 0805_HV 1634,3225.5 r0 top value=511
R134 "CRCW0805511RFKEA" 0805_HV 1995,1084 r90 top value=511
R135 "CRCW0603511RFKEA" 0603 2110,864 r0 top value=511
R136 "CRCW060310K0JNEA" 0603 2056,1785.52 r270 top value=10k
R137 "CRCW060310M0JNEA" 0603 1996,1215 r270 top value=10Meg
R138 "RT0603BRD0749K9L" 0603 1757,3329 r270 top value=49.9k
R139 "CRCW06035K10JNEA" 0603 1612,3338 r270 top value=5.1k
R140 "RT0603BRD0749K9L" 0603 1777,1677 r270 top value=49.9k
R141 "CRCW060320K0JNEA" 0603 1887,1677 r270 top value=20k
R142 "CRCW060320K0JNEA" 0603 1832,1677 r270 top value=20k
RT1 "MF51E103F3950" Thermistor_103AT-2 1642,4235 r270 top value="10.0k ohm"
RT2 "MF51E103F3950" Thermistor_103AT-2 1538,4235 r270 top value="10.0k ohm"
RT3 "MF51E103F3950" Thermistor_103AT-2 1330,4235 r270 top value="10.0k ohm"
RT4 "MF51E103F3950" Thermistor_103AT-2 1434,4235 r270 top value="10.0k ohm"
RT5 "TMP6131DECR" DEC0002A 1306.52,1334.51 r180 top
S1 "RS-032G05A3-SM RT" SW_RS-032G05A3-SM 2367,4382 r0 top
S2 "RS-032G05A3-SM RT" SW_RS-032G05A3-SM 2525,4642 r270 top
U1 "bq76952PFBR" PFB0048A_N 1154.34,3618.73 r270 top
U2 "TLV70433DBVT" DBV0005A_N 2118,4040 r90 top
U3 "MSP430FR2155TDBTR" DBT0038A_N 1849,3830 r180 top
U4 "TCAN1044DDFRQ1" DDF0008A-MFG 2294,3633 r0 top
U5 "LM5163DDAR" DDA0008E_M 1552,4861 r270 top

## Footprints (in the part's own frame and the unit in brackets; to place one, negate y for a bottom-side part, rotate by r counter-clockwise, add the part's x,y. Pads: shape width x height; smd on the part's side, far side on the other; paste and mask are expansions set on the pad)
0402 [mm] "0402 from SM-752 data"
  rect 0.8x0.6 smd: 1(-0.6,0) 2(0.6,0)
  silkscreen extent -1.22,-0.52 1.22,0.52, body extent -0.55,-0.3 0.55,0.3, height 0.6
0603 [mm] "0603 from SM-752 data"
  rect 1x0.95 smd: 1(-0.8,0) 2(0.8,0)
  silkscreen extent -1.52,-0.69 1.52,0.69, body extent -0.87,-0.47 0.87,0.47, height 1
0603S [mil]
  rect 20x35 smd: 1(-30,0) 2(30,0)
  silkscreen extent -10,-17 10,17, body extent -34,-19 34,19, height 39
0805_HV [mil] "0805 with 30mil clearance between pads"
  rect 50x63 smd: 1(-40,0) 2(40,0)
  silkscreen extent -74,-40 74,40, body extent -43,-29 43,29, height 57
0805_HV1 [mm] "Custom footprint based on analyzing multiple manufacturer recommendations"
  rrect10% 1x1.25 smd: 1(-1,0) 2(1,0)
  silkscreen extent -0.2,-0.75 0.2,0.75, body extent -1.1,-0.72 1.1,0.73, height 1.45
1206 [mm] "1206 from SM-752 data"
  rect 1.3x1.85 smd: 1(-1.45,0) 2(1.45,0)
  silkscreen extent -2.4,-1.21 2.4,1.21, body extent -1.7,-0.9 1.7,0.9, height 1.35
1206_180 [mm] "1206_180"
  rect 1.1x1.6 smd: 1(-1.7,0) 2(1.7,0)
  silkscreen extent -0.9,-1 0.9,1, body extent -1.75,-0.95 1.75,0.95, height 1.8
1206_190 [mm] "1206_190"
  rect 1.1x1.6 smd: 1(-1.7,0) 2(1.7,0)
  silkscreen extent -0.9,-1 0.9,1, body extent -1.75,-0.95 1.75,0.95, height 1.9
1206L [mm] "1206 from SM-752 data"
  rect 1.1x1.75 smd: 1(-1.35,0) 2(1.35,0)
  silkscreen extent -0.4,-0.77 0.4,0.77, body extent -1.7,-0.9 1.7,0.9, height 1.35
1210 [mm] "1210 from SM-752 data"
  rect 1.3x2.7 smd: 1(-1.45,0) 2(1.45,0)
  silkscreen extent -2.32,-1.57 2.32,1.57, body extent -1.7,-1.35 1.7,1.35, height 1.35
2512 [mm] "Chip Resistor, Body 6.3x3.2mm, IPC Medium Density"
  rect 1.3x3.4 smd: 1(-2.95,0) 2(2.95,0)
  silkscreen extent -1.9,-1.6 1.9,1.6, body extent -3.22,-1.67 3.22,1.67, height 0.71
DBT0038A_N [mm] "TSSOP, 38-Leads, Body 9.7x4.4mm, Pitch 0.5mm, IPC Medium Density"
  oval 1.4x0.3 smd: 1(-2.95,4.5) 2(-2.95,4) 3(-2.95,3.5) 4(-2.95,3) 5(-2.95,2.5) 6(-2.95,2) 7(-2.95,1.5) 8(-2.95,1) 9(-2.95,0.5) 10(-2.95,0) 11(-2.95,-0.5) 12(-2.95,-1) 13(-2.95,-1.5) 14(-2.95,-2) 15(-2.95,-2.5) 16(-2.95,-3) 17(-2.95,-3.5) 18(-2.95,-4) 19(-2.95,-4.5) 20(2.95,-4.5) 21(2.95,-4) 22(2.95,-3.5) 23(2.95,-3) 24(2.95,-2.5) 25(2.95,-2) 26(2.95,-1.5) 27(2.95,-1) 28(2.95,-0.5) 29(2.95,0) 30(2.95,0.5) 31(2.95,1) 32(2.95,1.5) 33(2.95,2) 34(2.95,2.5) 35(2.95,3) 36(2.95,3.5) 37(2.95,4) 38(2.95,4.5)
  silkscreen extent -3.5,-4.9 1.5,4.9, body extent -3.21,-4.85 3.21,4.85, height 1.2
DBV0005A_N [mm] "SOT23, 5-Leads, Body 2.9x1.6mm, Pitch 0.95mm, Lead Span 2.8mm, IPC Medium Density"
  rrect17% 1x0.6 smd: 1(-1.375,0.95) 2(-1.375,0) 3(-1.375,-0.95) 4(1.375,-0.95) 5(1.375,0.95)
  silkscreen extent -1.63,-1.55 0.38,1.55, body extent -1.42,-1.46 1.42,1.46, height 1.09
DDA0008E_M [mm]
  rrect15% 1.65x0.65 smd: 1(-2.825,1.905) 2(-2.825,0.635) 3(-2.825,-0.635) 4(-2.825,-1.905) 5(2.825,-1.905) 6(2.825,-0.635) 7(2.825,0.635) 8(2.825,1.905)
  rrect7% 2.95x4.9 smd paste-1.5 mask-1.5: 9(0,0)
  rrect4% 2.4x3.1 on Top Paste: 9(0,0)
  rrect4% 2.4x3.1 on Top Solder: 9(0,0)
  silkscreen extent -3.42,-2.52 1.4,2.5, body extent -3,-2.45 3,2.45, height 1.57
DDF0008A-MFG [mm]
  rrect22% 1.05x0.45 smd paste+0 mask+0: 1(-1.3,0.975) 2(-1.3,0.325) 3(-1.3,-0.325) 4(-1.3,-0.975) 5(1.3,-0.975) 6(1.3,-0.325) 7(1.3,0.325) 8(1.3,0.975)
  silkscreen extent -2.5,-1.48 0.4,1.48, body extent -1.92,-1.73 1.92,1.73, height 0.25
DEC0002A [mm] "X1SON-2"
  rrect57% 0.35x0.6 smd paste-0.5 mask-0.05: 1(-0.325,0) 2(0.325,0)
  rrect33% 0.3x0.5 on Top Paste: 1S(-0.35,0) 2S(0.35,0)
  body extent -0.5,-0.3 0.5,0.3, height 0.5
FCC_disclaimer [mil]
Fuse_0678L [mm] "SMD, 2-Leads, Body 9.8x3.05mm"
  rrect3% 3.81x4.06 smd: 1(-4.705,0) 2(4.705,0)
  silkscreen extent -2.4,-1.6 2.4,1.6, body extent -5,-1.59 5,1.59, height 3.18
FUSE_SFK-xx30x [mm] "Fuse"
  rect 7.4x1.2 smd paste+0 mask+0.07: 1(0,2.05) 3(0,-2.05)
  rect 0.75x3 smd paste+0 mask+0.07: 2(-5.575,0)
  Top Layer region: -5.2,1.5 -5.2,-1.5 -3.8,-0.35 -3.8,0.35
  silkscreen extent -4.75,-2.5 4.75,2.5, body extent -4.75,-2.5 4.75,2.5, height 2
HDR1X2 [mm] "Connector; Header; 2 Position"
  rect 1.5x1.5 hole 0.9: 1(0,0)
  round 1.5 hole 0.9: 2(2.54,0)
  silkscreen extent -1.27,-1.27 3.81,1.27
HDR1X4 [mm] "Connector; Header; 4 Position"
  rect 1.5x1.5 hole 0.9: 1(0,0)
  round 1.5 hole 0.9: 2(2.54,0) 3(5.08,0) 4(7.62,0)
  silkscreen extent -1.27,-1.27 8.89,1.27
HDR1X17 [mm] "Connector; Header; 17 Position"
  rect 1.5x1.5 hole 0.9: 1(0,0)
  round 1.5 hole 0.9: 2(2.54,0) 3(5.08,0) 4(7.62,0) 5(10.16,0) 6(12.7,0) 7(15.24,0) 8(17.78,0) 9(20.32,0) 10(22.86,0) 11(25.4,0) 12(27.94,0) 13(30.48,0) 14(33.02,0) 15(35.56,0) 16(38.1,0) 17(40.64,0)
  silkscreen extent -1.27,-1.27 41.91,1.27
HDR2X2 [mm] "Connector; Header; 2x2 Position"
  rect 1.5x1.5 hole 0.9: 1(0,0)
  round 1.5 hole 0.9: 2(0,2.54) 3(2.54,0) 4(2.54,2.54)
  silkscreen extent -1.27,-1.27 3.81,3.81
IEC_Caution_Small [mil]
  silkscreen extent -107,-93 107,92
KTT0002A_N [mm] "D2-PAK, 2-Leads, Body 9x10.1mm, Pitch 2.54mm, Lead Span 15.1mm, IPC Medium Density"
  rrect10% 3.5x1 smd: 1(-6.15,2.54) 3(-6.15,-2.54)
  rrect1% 8.4x8.65 smd paste-4.2: 2(3.75,0)
  silkscreen extent -7.75,-5.07 -1.78,5.07, body extent -6.68,-5.08 7.62,5.08, height 4.72
PFB0048A_N [mm] "Thin QFP, 48-Leads, Body 7x7mm, Pitch 0.5mm, IPC Medium Density"
  oval 1.45x0.3 smd: 1(-4.225,2.75) 2(-4.225,2.25) 3(-4.225,1.75) 4(-4.225,1.25) 5(-4.225,0.75) 6(-4.225,0.25) 7(-4.225,-0.25) 8(-4.225,-0.75) 9(-4.225,-1.25) 10(-4.225,-1.75) 11(-4.225,-2.25) 12(-4.225,-2.75) 25(4.225,-2.75) 26(4.225,-2.25) 27(4.225,-1.75) 28(4.225,-1.25) 29(4.225,-0.75) 30(4.225,-0.25) 31(4.225,0.25) 32(4.225,0.75) 33(4.225,1.25) 34(4.225,1.75) 35(4.225,2.25) 36(4.225,2.75)
  oval 0.3x1.45 smd: 13(-2.75,-4.225) 14(-2.25,-4.225) 15(-1.75,-4.225) 16(-1.25,-4.225) 17(-0.75,-4.225) 18(-0.25,-4.225) 19(0.25,-4.225) 20(0.75,-4.225) 21(1.25,-4.225) 22(1.75,-4.225) 23(2.25,-4.225) 24(2.75,-4.225) 37(2.75,4.225) 38(2.25,4.225) 39(1.75,4.225) 40(1.25,4.225) 41(0.75,4.225) 42(0.25,4.225) 43(-0.25,4.225) 44(-0.75,4.225) 45(-1.25,4.225) 46(-1.75,4.225) 47(-2.25,4.225) 48(-2.75,4.225)
  silkscreen extent -4.17,-2.75 2.75,3.58, body extent -4.5,-4.5 4.5,4.5, height 1.07
SMB [mil] "Molded Diode, 2-Leads, Body 5.4x3.6mm, IPC Medium Density, based on OnSemi component dimensions"
  rect 85x107.99 smd: 1(-87.01,0) 2(87.01,0)
  silkscreen extent -155,-82 125,82, body extent -106,-71 106,71, height 91
SMC [mil] "Molded Diode, 2-Leads, Body 6.9x5.8mm, IPC Medium Density, based on OnSemi component dimensions and land patterns"
  rect 110x150 smd: 1(-140.49,0) 2(140.49,0)
  silkscreen extent -221,-124 189,123, body extent -156,-116 156,116, height 91
SOD-123 [mm] "On Semi recommended land pattern"
  rect 0.915x1.22 smd: 1(-1.637,0) 2(1.637,0)
  silkscreen extent -2.74,-1.17 2.03,1.17, body extent -1.93,-0.9 1.93,0.9, height 1.35
SOD-123F [mm] "NXP recommended land pattern"
  rect 1.2x1.2 smd paste-0.05: 1(-1.4,0) 2(1.4,0)
  silkscreen extent -2.64,-1.12 2.01,1.12, body extent -1.8,-0.85 1.8,0.85, height 1.2
SOD-323 [mm] "NXP recommended land pattern"
  rect 0.6x0.6 smd paste-0.05: 1(-1.1,0) 2(1.1,0)
  silkscreen extent -2.06,-0.86 1.53,0.86, body extent -1.3,-0.67 1.3,0.68, height 1.1
SOD-523 [mm] "NXP Semiconductor recommended land pattern, nominal STEP model"
  rect 0.8x0.6 smd paste-0.05: 1(-0.55,0) 2(0.55,0)
  silkscreen extent -1.65,-0.66 1.2,0.66, body extent -0.8,-0.4 0.8,0.4, height 0.72
SOT-23 [mm] "SOT23, 3-Leads, Body 2.9x1.3mm, Pitch 0.95mm, Lead Span 2.5mm, IPC Medium Density"
  rrect50% 1x0.6 smd: 1(-1.2,0.95) 2(-1.2,-0.95) 3(1.2,0)
  silkscreen extent -1.63,-1.5 0.7,1.5, body extent -1.16,-1.45 1.21,1.45, height 1
SOT-323 [mm] "Diodes Inc recommended land pattern.  2016-02-24"
  rrect21% 0.6x0.47 smd: 1(-0.95,0.65) 2(-0.95,-0.65) 3(0.95,0)
  silkscreen extent -1.14,-1.22 0.77,1.22, body extent -1.13,-1.13 1.12,1.12, height 1.13
SSOT-6 [mm] "Fairchild"
  rect 1.1x0.7 smd: 1(-1.3,0.95) 2(-1.3,0) 3(-1.3,-0.95) 4(1.3,-0.95) 5(1.3,0) 6(1.3,0.95)
  silkscreen extent -0.85,-1.55 0.25,1.8, body extent -1.5,-1.5 1.5,1.5, height 1.1
SW_RS-032G05A3-SM [mm] "SMT, 2-Leads, Body 6x3.5mm, Pin Spacing 8mm"
  rect 2x2 smd: 1(-4,0) 2(4,0)
  silkscreen extent -3,-1.75 3,1.75, body extent -4,-1.75 4,1.75, height 4.3
Thermistor_103AT-2 [mil] "SEMITEC"
  rect 65x65 hole 35: 1(-50,0)
  round 65 hole 35: 2(50,0)
  body extent -78,-47 79,47, height 338
UUX_800x620 [mm] "SMD, 2-Leads, Dia 8mm"
  rect 4x2.5 smd: 1(-3.05,0) 2(3.05,0)
  silkscreen extent -4.25,-4.25 4.25,4.25, body extent -4.25,-4.25 4.25,4.25, height 6.51
WE-MAPI_3015 [mm] "SMD, 2-Leads, Body 3x3mm"
  rect 1.3x3.4 smd: 1(-1.05,0) 2(1.05,0)
  silkscreen extent -0.12,-1.7 0.12,1.7, body extent -1.6,-1.6 1.6,1.6, height 1.5
WE-PD_7345 [mm] "SMD Inductor, 2-Leads, Body 7,3x7,3mm"
  rect 1.6x2.2 smd: 1(-3.2,0) 2(3.2,0)
  silkscreen extent -3.65,-3.68 3.61,3.6, body extent -3.65,-3.68 3.65,3.6, height 4.49
WEEE_Minimum [mil] "WEEElie bin"
  silkscreen extent -95,-172 99,104
WL-SMCW_RED [mm] "WURTH"
  rect 0.8x0.8 smd: 1(-0.8,0) 2(0.8,0)
  silkscreen extent -1.9,-0.8 1.2,0.8, body extent -0.85,-0.45 0.85,0.45, height 0.8

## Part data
C1 C2 C3 C4 C5 C6 C7 C8 C9 C10 C11 C12 C13 C14 C20 C21 C22: "CAP, CERM, 0.22 μF, 50 V,+/- 10%, X7R, AEC-Q200 Grade 1, 0603", Cap_Case=0603, Manufacturer=MuRata, Supplier Part Number 1=490-5402-1-ND, TempCo=X7R, Tolerance_%=10, Value2=50V, ValueDisplayed=0.22μF
C15: "CAP, CERM, 2.2 μF, 100 V,+/- 10%, X7R, 1206", Cap_Case=1206, Manufacturer="Samsung Electro-Mechanics", Supplier Part Number 1=1276-3138-1-ND, TempCo=X7R, Tolerance_%=10, Value2=100V, ValueDisplayed=2.2μF
C16 C17 C23 C24 C33: "CAP, CERM, 100 pF, 100 V,+/- 5%, C0G/NP0, 0603", Cap_Case=0603, Manufacturer=MuRata, Supplier Part Number 1=490-1351-1-ND, TempCo=C0G/NP0, Tolerance_%=5, Value2=100V, ValueDisplayed=100pF
C18: "CAP, CERM, 1 μF, 25 V,+/- 10%, X7R, 0603", Cap_Case=0603, Manufacturer=TDK, Supplier Part Number 1=445-5956-1-ND, TempCo=X7R, Tolerance_%=10, Value2=25V, ValueDisplayed=1μF
C19 C37: "CAP, CERM, 2.2 μF, 16 V,+/- 10%, X7R, 0603", Cap_Case=0603, Manufacturer="Taiyo Yuden", Supplier Part Number 1=587-4864-1-ND, TempCo=X7R, Tolerance_%=10, Value2=16V, ValueDisplayed=2.2μF
C25 C26: "CAP, CERM, 1 μF, 16 V,+/- 10%, X7R, AEC-Q200 Grade 1, 0603", Cap_Case=0603, Manufacturer=MuRata, Supplier Part Number 1=490-5241-6-ND, TempCo=X7R, Tolerance_%=10, Value2=16V, ValueDisplayed=1μF
C27: "CAP, CERM, 0.022 μF, 50 V,+/- 10%, X7R, 0603", Cap_Case=0603, Manufacturer=MuRata, Supplier Part Number 1=490-1517-1-ND, TempCo=X7R, Tolerance_%=10, Value2=50V, ValueDisplayed=0.022μF
C28 C30 C31 C34 C35 C40: "CAP, CERM, 470 pF, 50 V,+/- 10%, X7R, 0603", Cap_Case=0603, Manufacturer=MuRata, Supplier Part Number 1=490-1489-1-ND, TempCo=X7R, Tolerance_%=10, Value2=50V, ValueDisplayed=470pF
C29: "CAP, CERM, 1 μF, 100 V,+/- 10%, X7R, 1206", Cap_Case=1206, Manufacturer=TDK, Supplier Part Number 1=445-4467-1-ND, TempCo=X7R, Tolerance_%=10, Value1="0.004575 ohm", Value2=100V, ValueDisplayed=1μF
C32 C38 C41 C42 C43: "CAP, CERM, 0.1 μF, 50 V,+/- 10%, X7R, 0603", Cap_Case=0603, Manufacturer=MuRata, Supplier Part Number 1=490-1519-1-ND, TempCo=X7R, Tolerance_%=10, Value2=50V, ValueDisplayed=0.1μF
C36: "CAP, CERM, 10 μF, 16 V,+/- 10%, X7R, 0805", Cap_Case=0805, Manufacturer="Samsung Electro-Mechanics", Supplier Part Number 1=1276-2872-1-ND, TempCo=X7R, Tolerance_%=10, Value2=16V, ValueDisplayed=10μF
C39: "CAP, CERM, 1000 pF, 50 V,+/- 5%, C0G/NP0, 0603", Cap_Case=0603, Manufacturer=MuRata, Supplier Part Number 1=490-1451-1-ND, TempCo=C0G/NP0, Tolerance_%=5, Value2=50V, ValueDisplayed=1000pF
C44 C45: "CAP, CERM, 4.7 μF, 100 V,+/- 10%, X7S, 1210", Cap_Case=1210, Manufacturer=TDK, Supplier Part Number 1=445-8912-1-ND, TempCo=X7S, Tolerance_%=10, Value2=100V, ValueDisplayed=4.7μF
C46 C55 C56 C57 C58 C59 C60: "CAP, CERM, 0.1 μF, 100 V,+/- 10%, X7R, 0603", Cap_Case=0603, Manufacturer=MuRata, Supplier Part Number 1=490-3285-1-ND, TempCo=X7R, Tolerance_%=10, Value2=100V, ValueDisplayed=0.1μF
C47: library part UUX2A4R7MCL1GS, "CAP, AL, 10 μF, 100 V, +/- 20%, SMD", Cap_Case=8x6.2mm, Manufacturer=Nichicon, Supplier Part Number 1=493-6282-1-ND, Tolerance_%=20, Value2=100V, ValueDisplayed=10μF
C48: library part GRM1885C1H560JA01D, "CAP, CERM, 56 pF, 50 V,+/- 5%, C0G/NP0, 0603", Cap_Case=0603, Manufacturer=MuRata, Supplier Part Number 1=490-1421-1-ND, TempCo=C0G/NP0, Tolerance_%=5, Value2=50V, ValueDisplayed=56pF
C49: "CAP, CERM, 2200 pF, 50 V,+/- 10%, X7R, 0402", Cap_Case=0402, Manufacturer=MuRata, Supplier Part Number 1=490-1305-1-ND, TempCo=X7R, Tolerance_%=10, Value2=50V, ValueDisplayed=2200pF
C50: "CAP, CERM, 100 pF, 50 V,+/- 5%, C0G/NP0, 0603", Cap_Case=0603, Manufacturer=MuRata, Supplier Part Number 1=490-1427-1-ND, TempCo=C0G/NP0, Tolerance_%=5, Value2=50V, ValueDisplayed=100pF
C51: "CAP, CERM, 1500 pF, 50 V,+/- 10%, X7R, 0402", Cap_Case=0402, Manufacturer=MuRata, Supplier Part Number 1=490-3245-1-ND, TempCo=X7R, Tolerance_%=10, Value2=50V, ValueDisplayed=1500pF
C52 C53 C54: "CAP, CERM, 4.7 μF, 16 V,+/- 10%, X7R, 0805", Cap_Case=0805, Manufacturer=MuRata, Supplier Part Number 1=490-4522-1-ND, TempCo=X7R, Tolerance_%=10, Value1="0.006 ohm", Value2=16V, ValueDisplayed=4.7μF
D1 D2 D3 D4 D5 D6 D7 D8 D12 D13 D14 D15 D16 D17 D18 D19: "Diode, Zener, 5.6 V, 300 mW, SOD-523", Manufacturer="Diodes Inc.", Power_W=0.3, Supplier Part Number 1=BZT52C5V6TDICT-ND, Value1=0.3W
D9: "Diode, Schottky, 30 V, 0.2 A, SOD-323", Manufacturer="Diodes Inc.", Supplier Part Number 1=BAT42WSDICT-ND, Value1=0.2A, Value2=1V
D10 D21 D22: "Diode, Zener, 3.6 V, 500 mW, SOD-123", Manufacturer="ON Semiconductor", Power_W=0.5, Supplier Part Number 1=MMSZ4685T1GOSCT-ND, Value1=0.5W
D11 D20 D30 D37: "Diode, Switching, 100 V, 0.25 A, SOD-523", Manufacturer=Nexperia, Supplier Part Number 1=568-1603-1-ND, Value1=0.25A, Value2=1.25V
D23 D24 D25: "LED, Red, SMD", Color=Red, Manufacturer="Wurth Elektronik", Power_TotalModule=0.072, Supplier Part Number 1=732-4978-1-ND, Value1=0.072W, Value2=2V
D26: "Diode, Zener, 5.6 V, 500 mW, SOD-123", Manufacturer="ON Semiconductor", Power_W=0.5, Supplier Part Number 1=MMSZ4690T1GOSCT-ND, Value1=0.5W
D27: library part NUP2105LT1G, "Diode, TVS, Bi, 24 V, SOT-23", Manufacturer="ON Semiconductor", Power_W=0.35, Supplier Part Number 1=NUP2105LT1GOSCT-ND, Value1=0.35W
D28 D29: "Diode, Schottky, 20 V, 1 A, SOD-123F", Manufacturer=Nexperia, Supplier Part Number 1=568-4112-1-ND, Value1=1A, Value2=0.43V
D31: "Diode, TVS, Uni, 60 V, 96.8 Vc, SMB", Manufacturer="Diodes Inc.", Power_W=5, Supplier Part Number 1=SMBJ60A-FDICT-ND, Value1=5W
D32 D34 D39 D40: "Diode, Zener, 16 V, 500 mW, SOD-123", Manufacturer="Diodes Inc.", Power_W=0.5, Supplier Part Number 1=MMSZ5246B-FDICT-ND, Value1=0.5W
D33 D35 D41 D43: library part MMSZ5263BT1G, "Diode, Zener, 75V, 500 mW, AEC-Q101, SOD-123", Manufacturer="ON Semiconductor", Power_W=0.5, Supplier Part Number 1=MMSZ5263BT1GOSCT-ND, Value1=0.5W
D36 D42 D44 D45 D46: "Diode, Schottky, 100 V, 0.15 A, SOD-123", Manufacturer="Diodes Inc.", Supplier Part Number 1=BAT46W-7FDICT-ND, Value1=0.15A, Value2=0.6V
D38: "Diode, Zener, 5.1 V, 200 mW, SOD-323", Manufacturer="Diodes Inc.", Power_W=0.2, Supplier Part Number 1=BZT52C5V1S-FDICT-ND, Value1=0.2W
D47: "Diode, Ultrafast, 200 V, 3 A, SMC", Manufacturer=Vishay-Semiconductor, Supplier Part Number 1=ES3D-E3/57TGICT-ND, Value1=3A, Value2=0.9V
F1: library part SFK-5030, Irating_A=30, Manufacturer=POLYTRONICS
F2: library part 0678L9150-02, "Fuse, 30 A, 250 VAC, 72 VDC, SMD", Irating_A=15, Manufacturer="Bel Fuse", Supplier Part Number 1=507-2062-1-ND
L1: "Inductor, Shielded, 1 μH, 2.7 A, 0.039 ohm, SMD", Manufacturer="Wurth Elektronik", Supplier Part Number 1=732-4863-1-ND, Value1="0.039 ohm", Value2=2.7A, ValueDisplayed=10μH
